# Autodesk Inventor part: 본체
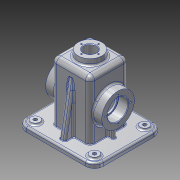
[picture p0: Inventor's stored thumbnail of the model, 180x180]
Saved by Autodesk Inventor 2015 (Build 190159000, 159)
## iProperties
Created: 2016-02
Part Number: 본체
Material: 알루미늄 6061
Document SubType Name: Modeling
Designer: Administrator
Density: 2.7 g/cm^3
Appearance: 알루미늄 - 평지
Mass: 803.294 g
Surface Area: 909.625 cm^2
Volume: 297.516 cm^3
Author: Administrator
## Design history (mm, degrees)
sketch "스케치1"
  geometry: L1 (-65, -57.5)-(65, -57.5); L2 (65, -57.5)-(65, 57.5); L3 (65, 57.5)-(-65, 57.5); L4 (-65, 57.5)-(-65, -57.5); L5 (-65, -57.5)-(65, 57.5); L6 (65, -57.5)-(-65, 57.5); 1 further point
  constraints: 12 end point, 2 midpoint, 2 parallel, 1 horizontal, 1 perpendicular
  dimensions: "d0" = 130 distance of L2.end L3.end; "d1" = 115 distance of L1.end L2.end
extrude "돌출1" new body sketch "스케치1" distance "d2" = 8; taper "d3" = 0 deg
sketch "스케치2"
  geometry: L1 (-32.5, 32.5)-(32.5, 32.5); L2 (32.5, 32.5)-(32.5, -32.5); L3 (32.5, -32.5)-(-32.5, -32.5); L4 (-32.5, -32.5)-(-32.5, 32.5); L5 (-32.5, 32.5)-(32.5, -32.5); L6 (32.5, 32.5)-(-32.5, -32.5); 1 further point
  constraints: 12 end point, 2 midpoint, 2 parallel, 1 horizontal, 1 perpendicular
  dimensions: "d4" = 65 distance of L1.start L1.end; "d5" = 65 distance of L1.end L2.end
extrude "돌출2" join sketch "스케치2" distance "d6" = 100; taper "d7" = 0 deg
sketch "스케치3"
  geometry: L1 (-114.421, 32.5)-(34.834, 32.5); L2 (8, -25)-(0, -25) reference; L3 (0, -25)-(0, 0) reference; L4 (0, 0)-(-100, 0) reference; L5 (-100, 0)-(-100, 65) reference; L6 (-100, 65)-(0, 65) reference; L7 (0, 65)-(0, 90) reference; L8 (0, 90)-(8, 90) reference; L9 (8, 90)-(8, -25) reference; L10 (0, 0)-(0, 65) reference; C1 r 27.5 at (-45, 32.5); 1 further point
  constraints: 2 end point, 1 centre point, 1 horizontal, 1 point on line
  dimensions: "d8" = 65 diameter of L4 L1; "d9" = 55 diameter of C1; "d10" = 53 distance from line of L9 C1.centre
extrude "돌출3" join sketch "스케치3" distance "d11" = 15; taper "d12" = 0 deg
sketch "스케치4"
  geometry: L1 (-65, 0)-(-65, 8) reference; L2 (-65, 8)-(-32.5, 8) reference; L3 (-32.5, 8)-(-32.5, 25.5) reference; L4 (-32.5, 25.5)-(-47.5, 25.5) reference; L5 (-47.5, 25.5)-(-47.5, 80.5) reference; L6 (-47.5, 80.5)-(-32.5, 80.5) reference; L7 (-32.5, 80.5)-(-32.5, 108) reference; L8 (-32.5, 108)-(32.5, 108) reference; L9 (32.5, 108)-(32.5, 80.5) reference; L10 (32.5, 80.5)-(47.5, 80.5) reference; L11 (47.5, 80.5)-(47.5, 25.5) reference; L12 (47.5, 25.5)-(32.5, 25.5) reference; L13 (32.5, 25.5)-(32.5, 8) reference; L14 (32.5, 8)-(65, 8) reference; L15 (65, 8)-(65, 0) reference; L16 (65, 0)-(-65, 0) reference; L17 (-27.5, 103)-(27.5, 103); L18 (27.5, 103)-(27.5, 0); L19 (27.5, 0)-(-27.5, 0); L20 (-27.5, 0)-(-27.5, 103); L21 (0, 108)-(0, 0)
  constraints: 10 end point, 2 parallel, 1 horizontal, 1 midpoint, 1 perpendicular, 1 point on line, 1 vertical
  dimensions: "d14" = 55 diameter of L20 L21; "d15" = 103 distance between parallel lines of L16 L17; "d16" = 55 diameter of L18 L21
extrude "돌출4" cut sketch "스케치4" stored distance "d17" = 55; taper "d18" = 0 deg
sketch "스케치5"
  geometry: L1 (-57.5, 0)-(-57.5, 8) reference; L2 (-57.5, 8)-(-32.5, 8) reference; L3 (-32.5, 8)-(-32.5, 108) reference; L4 (-32.5, 108)-(32.5, 108) reference; L5 (32.5, 108)-(32.5, 8) reference; L6 (32.5, 8)-(57.5, 8) reference; L7 (57.5, 8)-(57.5, 0) reference; L8 (57.5, 0)-(27.5, 0) reference; L9 (27.5, 0)-(27.5, 103) reference; L10 (27.5, 103)-(-27.5, 103) reference; L11 (-27.5, 103)-(-27.5, 0) reference; L12 (-27.5, 0)-(-57.5, 0) reference; L13 (-47.5, 8)-(-32.5, 93.069); L14 (-32.5, 8)-(-32.5, 108) reference; L15 (-32.5, 93.069)-(-32.5, 8); L16 (-57.5, 8)-(57.5, 8) reference; L17 (-32.5, 8)-(-47.5, 8); 1 further point
  constraints: 6 end point, 2 point on line, 1 collinear, 1 perpendicular
  dimensions: "d19" = 10 distance from line of L1 L13.start; "d20" = 100 deg angle of L13 L2
extrude "돌출5" join sketch "스케치5" stored distance "d21" = 10; taper "d22" = 0 deg
sketch "스케치6"
  geometry: L1 (-32.5, 25.5)-(-47.5, 25.5) reference; L2 (-47.5, 25.5)-(-47.5, 80.5) reference; L3 (-47.5, 80.5)-(-32.5, 80.5) reference; L4 (-32.5, 80.5)-(-32.5, 108) reference; L5 (-32.5, 108)-(32.5, 108) reference; L6 (32.5, 108)-(32.5, 80.5) reference; L7 (32.5, 80.5)-(47.5, 80.5) reference; L8 (47.5, 80.5)-(47.5, 25.5) reference; L9 (47.5, 25.5)-(32.5, 25.5) reference; L10 (32.5, 25.5)-(32.5, 8) reference; L11 (32.5, 8)-(65, 8) reference; L12 (65, 8)-(65, 0) reference; L13 (65, 0)-(27.5, 0) reference; L14 (27.5, 0)-(27.5, 103) reference; L15 (27.5, 103)-(-27.5, 103) reference; L16 (-27.5, 103)-(-27.5, 0) reference; L17 (-27.5, 0)-(-65, 0) reference; L18 (-65, 0)-(-65, 8) reference; L19 (-65, 8)-(-32.5, 8) reference; L20 (-32.5, 8)-(-32.5, 25.5) reference; L21 (65, 8)-(-65, 8) reference; L22 (42.5, 8)-(-42.5, 8); L23 (47.5, 25.5)-(32.5, 25.5) reference; L24 (-42.5, 8)-(-42.5, 30.849); L25 (-42.5, 30.849)-(42.5, 30.849); L26 (42.5, 30.849)-(42.5, 8); 1 further point
  constraints: 8 end point, 2 perpendicular, 2 point on line, 1 vertical
  dimensions: "d25" = 15 distance between parallel lines of L14 L26; "d26" = 15 distance between parallel lines of L16 L24; "d27" = 22.84869 distance between parallel lines of L21 L25
extrude "돌출6" join sketch "스케치6" stored distance "d28" = 6; taper "d29" = 0 deg
sketch "스케치7"
  geometry: L1 (-27.5, -27.5)-(27.5, -27.5) reference; L2 (27.5, -27.5)-(27.5, 27.5) reference; L3 (27.5, 27.5)-(-27.5, 27.5) reference; L4 (-27.5, 27.5)-(-27.5, -27.5) reference; L5 (65, 57.5)-(65, -57.5) reference; L6 (65, -57.5)-(-65, -57.5) reference; L7 (-65, -57.5)-(-65, 57.5) reference; L8 (-65, 57.5)-(65, 57.5) reference; L9 (-60, 52.5)-(60, 52.5); L10 (60, 52.5)-(60, -52.5); L11 (60, -52.5)-(-60, -52.5); L12 (-60, -52.5)-(-60, 52.5); L13 (-60, 52.5)-(60, -52.5); L14 (60, 52.5)-(-60, -52.5); 1 further point
  constraints: 12 end point, 2 midpoint, 2 parallel, 1 horizontal, 1 perpendicular
  dimensions: "d30" = 120 distance of L9.start L9.end; "d31" = 105 distance of L9.end L10.end
extrude "돌출7" join sketch "스케치7" distance "d32" = 2; taper "d33" = 0 deg
sketch "스케치8"
  geometry: L1 (-60, 52.5)-(60, 52.5) reference; L2 (60, 52.5)-(60, -52.5) reference; L3 (60, -52.5)-(-60, -52.5) reference; L4 (-60, -52.5)-(-60, 52.5) reference; L5 (27.5, -27.5)-(-27.5, -27.5); L6 (-27.5, -27.5)-(-27.5, 27.5); L7 (-27.5, 27.5)-(27.5, 27.5); L8 (27.5, 27.5)-(27.5, -27.5); L9 (27.5, -27.5)-(-27.5, 27.5); L10 (-27.5, -27.5)-(27.5, 27.5); 1 further point
  constraints: 12 end point, 2 midpoint, 2 parallel, 1 horizontal, 1 perpendicular
  dimensions: "d34" = 55 distance of L6.end L7.end; "d35" = 55 distance of L7.end L5.start
extrude "돌출8" cut sketch "스케치8" distance "d36" = 55; taper "d37" = 0 deg
fillet "모깎기1" dims "d38" = 10
fillet "모깎기2" dims "d39" = 15
sketch "스케치10"
  geometry: L1 (50, -57.5)-(-50, -57.5) reference; L2 (-65, -42.5)-(-65, 42.5) reference; L3 (-50, 57.5)-(50, 57.5) reference; L4 (65, 42.5)-(65, -42.5) reference; L5 (-42.5, -3)-(-42.5, 3) reference; L6 (-42.5, 3)-(-32.5, 3) reference; L7 (-32.5, 3)-(-32.5, 32.5) reference; L8 (-32.5, 32.5)-(-5, 32.5) reference; L9 (-5, 32.5)-(-5, 47.5) reference; L10 (-5, 47.5)-(5, 47.5) reference; L11 (5, 47.5)-(5, 32.5) reference; L12 (5, 32.5)-(32.5, 32.5) reference; L13 (32.5, 32.5)-(32.5, 3) reference; L14 (32.5, 3)-(42.5, 3) reference; L15 (42.5, 3)-(42.5, -3) reference; L16 (42.5, -3)-(32.5, -3) reference; L17 (32.5, -3)-(32.5, -32.5) reference; L18 (32.5, -32.5)-(5, -32.5) reference; L19 (5, -32.5)-(5, -47.5) reference; L20 (5, -47.5)-(-5, -47.5) reference; L21 (-5, -47.5)-(-5, -32.5) reference; L22 (-5, -32.5)-(-32.5, -32.5) reference; L23 (-32.5, -32.5)-(-32.5, -3) reference; L24 (-32.5, -3)-(-42.5, -3) reference; L25 (27.5, -27.5)-(27.5, 27.5) reference; L26 (27.5, 27.5)-(-27.5, 27.5) reference; L27 (-27.5, 27.5)-(-27.5, -27.5) reference; L28 (-27.5, -27.5)-(27.5, -27.5) reference; C1 r 7.5 at (50, -42.5); A1 r 15 centre (50, -42.5) between (50, -57.5) and (65, -42.5) reference; A2 r 15 centre (-50, -42.5) between (-65, -42.5) and (-50, -57.5) reference; A3 r 15 centre (-50, 42.5) between (-50, 57.5) and (-65, 42.5) reference; A4 r 15 centre (50, 42.5) between (65, 42.5) and (50, 57.5) reference; 1 further point
  constraints: 1 centre point, 1 coincident
  dimensions: "d40" = 15 diameter of C1
extrude "돌출9" join sketch "스케치10" distance "d41" = 3; taper "d42" = 0 deg
fillet "모깎기3" dims "d43" = 3
hole "구멍1" diameter "d46" = 6; stored, may be unused: countersink angle "d50" = 90 deg, drill point angle "d52" = 118 deg; dims "d44" = 10, "d45" = 10, "d47" = 6, "d48" = 4, "d49" = 2, "d51" = 8
node "작업 평면1"
sketch "스케치11"
  geometry: C1 r 20 at (0, 0); 1 further point
  constraints: 1 centre point, 1 coincident
  dimensions: "d60" = 40 diameter of C1
extrude "돌출10" join sketch "스케치11" stored distance "d61" = 3; taper "d62" = 0 deg
feature "면 기울기1" dims angle "d63" = 5 deg
fillet "모깎기4" dims "d64" = 8
fillet "모깎기6" dims "d66" = 8
sketch "스케치12"
  geometry: L1 (-45, 32.302)-(-45, -32.302) reference; L2 (-42, -35.429)-(-42, -40.842) reference; L3 (-42, -40.842)-(-55, -40.842) reference; L4 (-55, -40.842)-(-55, 40.842) reference; L5 (-55, 40.842)-(-42, 40.842) reference; L6 (-42, 40.842)-(-42, 35.429) reference; L7 (-53, -57.5)-(-53, -52.5) reference; L8 (-53, -52.5)-(-55, -52.5) reference; L9 (-55, -52.5)-(-55, -44.158) reference; L10 (-55, -44.158)-(-42, -44.158) reference; L11 (-42, -44.158)-(-42, -49.571) reference; L12 (-45, -52.698)-(-45, -57.5) reference; L13 (-45, -57.5)-(-53, -57.5) reference; L14 (-53, 52.5)-(-53, 57.5) reference; L15 (-53, 57.5)-(-45, 57.5) reference; L16 (-45, 57.5)-(-45, 52.698) reference; L17 (-42, 49.571)-(-42, 44.158) reference; L18 (-42, 44.158)-(-55, 44.158) reference; L19 (-55, 44.158)-(-55, 52.5) reference; L20 (-55, 52.5)-(-53, 52.5) reference; C1 r 27.5 at (0, 0) reference; C2 r 17.5 at (0, 0); 1 further point
  constraints: 1 centre point, 1 coincident, 4 other
  dimensions: "d67" = 35 diameter of C2
extrude "돌출11" cut sketch "스케치12" distance "d68" = 17; taper "d69" = 0 deg
sketch "스케치13"
  geometry: L1 (-55, -52.5)-(-55, 52.5) reference; L2 (-55, 52.5)-(-53, 52.5) reference; L3 (-53, 52.5)-(-53, 57.5) reference; L4 (-53, 57.5)-(-45, 57.5) reference; L5 (-45, 57.5)-(-45, 29.792) reference; L6 (-45, 29.792)-(47, 29.792) reference; L7 (52.292, 24.5)-(52.292, -24.5) reference; L8 (47, -29.792)-(-45, -29.792) reference; L9 (-45, -29.792)-(-45, -57.5) reference; L10 (-45, -57.5)-(-53, -57.5) reference; L11 (-53, -57.5)-(-53, -52.5) reference; L12 (-53, -52.5)-(-55, -52.5) reference; C1 r 17.5 at (0, 0) reference; C2 r 15 at (0, 0); A1 r 5.292 centre (47, 24.5) between (52.292, 24.5) and (47, 29.792) reference; A2 r 5.292 centre (47, -24.5) between (47, -29.792) and (52.292, -24.5) reference; 1 further point
  constraints: 1 centre point, 1 coincident
  dimensions: "d70" = 30 diameter of C2
extrude "돌출12" cut sketch "스케치13" stored distance "d71" = 17; taper "d72" = 0 deg
sketch "스케치14"
  geometry: C1 r 10.5 at (0, 0); 1 further point
  constraints: 1 centre point, 1 coincident
  dimensions: "d73" = 21 diameter of C1
extrude "돌출13" cut sketch "스케치14" stored distance "d74" = 17; taper "d75" = 0 deg
chamfer "모따기1" distance "d76" = 1; stored, may be unused: second distance "d77" = 2, angle "d78" = 45 deg
fillet "모깎기7" dims "d79" = 0.3
fillet "모깎기9" dims "d81" = 3
fillet "모깎기10" dims "d82" = 3
fillet "모깎기11" dims "d83" = 3
sketch "스케치16"
  geometry: L1 (-42, 44.158)-(-55, 44.158) reference; L2 (-55, 44.158)-(-55, 52.5) reference; L3 (-55, 52.5)-(-53, 52.5) reference; L4 (-53, 52.5)-(-53, 57.5) reference; L5 (-53, 57.5)-(-48, 57.5) reference; L6 (-45, 54.5)-(-45, 52.698) reference; L7 (-42, 49.571)-(-42, 44.158) reference; L8 (-42, -40.842)-(-55, -40.842) reference; L9 (-55, -40.842)-(-55, 40.842) reference; L10 (-55, 40.842)-(-42, 40.842) reference; L11 (-42, 40.842)-(-42, 35.429) reference; L12 (-45, 32.302)-(-45, -32.302) reference; L13 (-42, -35.429)-(-42, -40.842) reference; L14 (-53, -57.5)-(-53, -52.5) reference; L15 (-53, -52.5)-(-55, -52.5) reference; L16 (-55, -52.5)-(-55, -44.158) reference; L17 (-55, -44.158)-(-42, -44.158) reference; L18 (-42, -44.158)-(-42, -49.571) reference; L19 (-45, -52.698)-(-45, -54.5) reference; L20 (-48, -57.5)-(-53, -57.5) reference; C1 r 18.5 at (0, 0) reference; C2 r 27.5 at (0, 0) reference; A1 r 3 centre (-48, 54.5) between (-45, 54.5) and (-48, 57.5) reference; A2 r 3 centre (-48, -54.5) between (-48, -57.5) and (-45, -54.5) reference; 2 further points
  constraints: 4 other
  dimensions: "d84" = 0 vertical distance of C1.centre point (21, 0); "d85" = 21 distance of C2.centre point (21, 0)
hole "구멍2" sketch "스케치16" at (21, 0) diameter "d86" = 3.242; stored, may be unused: countersink angle "d90" = 90 deg, drill point angle "d92" = 118 deg; dims "d87" = 8, "d88" = 4, "d89" = 2, "d91" = 10
sketch "스케치17"
  geometry: C1 r 11.5 at (0, 0) reference; C2 r 20 at (0, 0) reference; 2 further points
  dimensions: "d96" = 0 horizontal distance of point (0, 0) point (0, -14.5); "d97" = 14.5 distance of point (0, 0) point (0, -14.5)
hole "구멍3" sketch "스케치17" at (0, -14.5) diameter "d98" = 2.459; stored, may be unused: countersink angle "d102" = 90 deg, drill point angle "d104" = 118 deg; dims "d99" = 7, "d100" = 4, "d101" = 2, "d103" = 9
node "작업 평면2"
fillet "모깎기12" dims "d112" = 3
fillet "모깎기15" dims "d115" = 3
fillet "모깎기17" dims "d117" = 3
fillet "모깎기18" dims "d118" = 3
fillet "모깎기19" dims "d119" = 3
fillet "모깎기20" dims "d120" = 1
fillet "모깎기21" dims "d121" = 3
sketch "스케치19"
  geometry: L1 (0, 57)-(-91, 57) reference; L2 (18, 44.5)-(18, 4.5) reference; 2 further points
  constraints: 1 other
  dimensions: "d122" = 26 distance from line of L2 point (-8, 24.5); "d123" = 32.5 distance from line of L1 point (-8, 24.5)
feature "엠보싱2" sketch "스케치19" dims "d124" = 0.5, "d125" = 0
node "솔리드1"
mirror "대칭1"
mirror "대칭2"
pattern_linear "직사각형 패턴1" dims "d55" = 85
mirror "대칭3"
pattern_circular "원형 패턴1" dims angle "d94" = 360 deg
mirror "대칭4"
pattern_circular "원형 패턴2" dims angle "d106" = 360 deg
mirror "대칭5"
node "절단 모서리 투영1"
node "절단 모서리 투영2"
node "절단 모서리 투영3"
node "절단 모서리 투영4"
node "절단 모서리 투영5"
node "절단 모서리 투영6"
node "절단 모서리 투영7"
node "절단 모서리 투영8"
node "절단 모서리 투영9"
node "절단 모서리 투영10"
node "절단 모서리 투영11"
